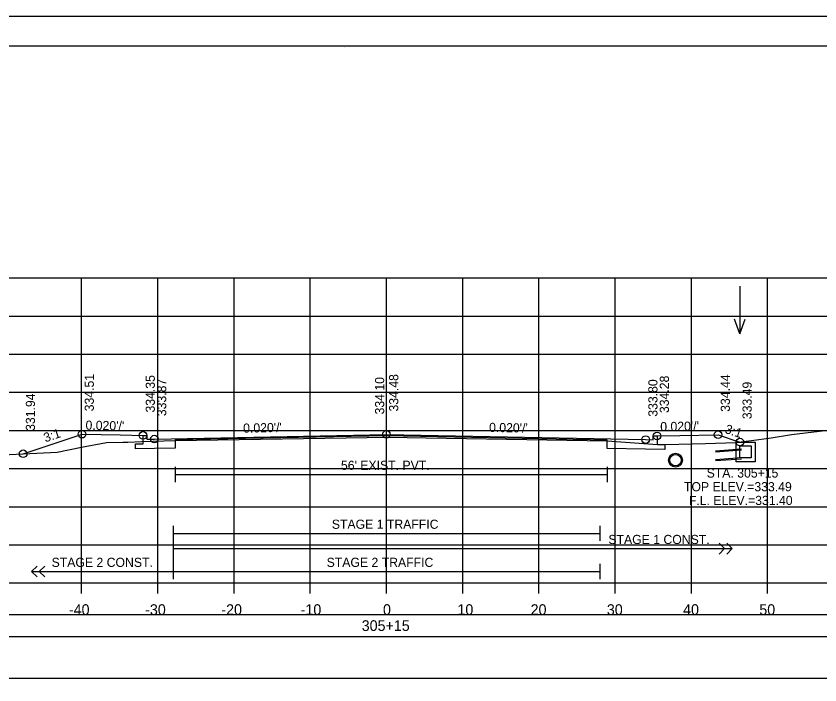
# Model space of a CAD drawing. Extents: x 1368122 to 1710785, y 373130 to 557566.
# Drawn here: x 1369307 to 1369412.4, y 373469.3 to 373557 of the extents above; entities that cross this region are included whole.
import ezdxf

# ---------------------------------------------------------------- set-up
doc = ezdxf.new("R2010")
doc.units = 0
for name, color, linetype in [('R_Alt Surface', 7, 'Continuous'), ('R_Axis', 7, 'Continuous'), ('R_Axis Annot', 7, 'Continuous'), ('R_Border', 7, 'Continuous'), ('R_Exist Surface', 7, 'Continuous'), ('R_Fin Surface', 7, 'Continuous'), ('R_Grid', 7, 'Continuous'), ('R_No Plot', 7, 'Continuous'), ('R_Striping', 7, 'Continuous'), ('R_Water', 7, 'Continuous'), ('R_Water Annot', 7, 'Continuous'), ('R_Xsect Elev', 7, 'Continuous'), ('R_Xsect Slope', 7, 'Continuous')]:
    doc.layers.add(name, color=color, linetype=linetype)

msp = doc.modelspace()

# ---------------------------------------------------------------- linework, layer by layer
for points in [[(1369206.41, 373475.64), (1369504.71, 373475.64), (1369504.71, 373478.46), (1369206.41, 373478.46)], [(1369206.41, 373470.17), (1369504.71, 373470.17), (1369504.71, 373475.58), (1369206.41, 373475.58)]]:
    msp.add_lwpolyline(points, close=True)
at = {"layer": 'R_Alt Surface'}
for points in [[(1369391.06, 373501.93), (1369391.06, 373500.84), (1369392.06, 373500.82), (1369392.06, 373500.15), (1369389.56, 373500.2), (1369384.5, 373500.3), (1369384.5, 373501.38), (1369355.56, 373501.96), (1369327.83, 373501.4), (1369327.83, 373500.32), (1369325.12, 373500.27), (1369322.62, 373500.22), (1369322.62, 373500.89), (1369323.62, 373500.91), (1369323.62, 373502)], [(1369327.83, 373497.88), (1369327.83, 373495.88)], [(1369384.5, 373497.88), (1369384.5, 373495.88)], [(1369327.83, 373496.88), (1369384.5, 373496.88)]]:
    msp.add_lwpolyline(points, dxfattribs=at)
at = {"layer": 'R_Axis'}
for p, q in [((1369205.56, 373482.65), (1369505.56, 373482.65)), ((1369315.56, 373481.25), (1369315.56, 373482.65)), ((1369325.56, 373481.25), (1369325.56, 373482.65)), ((1369335.56, 373481.25), (1369335.56, 373482.65)), ((1369345.56, 373481.25), (1369345.56, 373482.65)), ((1369355.56, 373481.25), (1369355.56, 373482.65)), ((1369365.56, 373481.25), (1369365.56, 373482.65)), ((1369375.56, 373481.25), (1369375.56, 373482.65)), ((1369385.56, 373481.25), (1369385.56, 373482.65)), ((1369395.56, 373481.25), (1369395.56, 373482.65)), ((1369405.56, 373481.25), (1369405.56, 373482.65))]:
    msp.add_line(p, q, dxfattribs=at)
at = {"layer": 'R_Border'}
for p, q in [((1369197.56, 373553.11), (1369513.74, 373553.11)), ((1369350.08, 373552.85), (1369350.08, 373552.85)), ((1369350.08, 373552.85), (1369350.08, 373552.85))]:
    msp.add_line(p, q, dxfattribs=at)
at = {"layer": 'R_Exist Surface'}
msp.add_lwpolyline([(1369301.59, 373499.29), (1369312.36, 373499.8), (1369315.54, 373500.47), (1369318.82, 373501.08), (1369320.99, 373501.12), (1369321.63, 373501.13), (1369323.42, 373501.18), (1369327.83, 373501.33), (1369350.27, 373501.66), (1369355.77, 373501.75), (1369360.75, 373501.67), (1369384.5, 373501.3), (1369391.13, 373500.82), (1369392.16, 373500.75), (1369392.17, 373500.79), (1369397.43, 373500.95), (1369401.41, 373501.06), (1369403.44, 373501.34), (1369406.04, 373501.7), (1369408.7, 373502.11), (1369423.73, 373503.92)], dxfattribs=at)
at = {"layer": 'R_Fin Surface'}
msp.add_lwpolyline([(1369307.9, 373499.59), (1369315.62, 373502.16), (1369320.62, 373502.06), (1369323.62, 373502), (1369324.12, 373502), (1369324.12, 373501.5), (1369325.12, 373501.52), (1369355.56, 373502.13), (1369389.56, 373501.45), (1369390.56, 373501.43), (1369390.56, 373501.93), (1369391.06, 373501.93), (1369394.06, 373501.99), (1369399.06, 373502.09), (1369401.92, 373501.13)], dxfattribs=at)
at = {"layer": 'R_Grid'}
for p, q in [((1369205.56, 373522.65), (1369505.56, 373522.65)), ((1369315.56, 373482.65), (1369315.56, 373522.65)), ((1369325.56, 373482.65), (1369325.56, 373522.65)), ((1369335.56, 373482.65), (1369335.56, 373522.65)), ((1369345.56, 373482.65), (1369345.56, 373522.65)), ((1369355.56, 373482.65), (1369355.56, 373522.65)), ((1369365.56, 373482.65), (1369365.56, 373522.65)), ((1369375.56, 373482.65), (1369375.56, 373522.65)), ((1369385.56, 373482.65), (1369385.56, 373522.65)), ((1369395.56, 373482.65), (1369395.56, 373522.65)), ((1369405.56, 373482.65), (1369405.56, 373522.65)), ((1369205.56, 373517.65), (1369505.56, 373517.65)), ((1369205.56, 373512.65), (1369505.56, 373512.65)), ((1369205.56, 373507.65), (1369505.56, 373507.65)), ((1369205.56, 373502.65), (1369505.56, 373502.65)), ((1369205.56, 373497.65), (1369505.56, 373497.65)), ((1369205.56, 373492.65), (1369505.56, 373492.65)), ((1369205.56, 373487.65), (1369505.56, 373487.65)), ((1369205.56, 373482.65), (1369505.56, 373482.65))]:
    msp.add_line(p, q, dxfattribs=at)
at = {"layer": 'R_No Plot'}
for p, q in [((1369185.16, 373557), (1369518.49, 373557)), ((1369402.15, 373500.19), (1369398.72, 373499.94)), ((1369402.15, 373498.9), (1369398.72, 373498.65))]:
    msp.add_line(p, q, dxfattribs=at)
for points in [[(1369185.15, 373557), (1369518.49, 373557), (1369518.49, 373343.66), (1369185.15, 373343.66)], [(1369431.48, 373553.11), (1369451.1, 373553.11), (1369451.1, 373543.23), (1369467.21, 373543.23), (1369490.41, 373543.23), (1369490.53, 373515.07), (1369513.74, 373515.07), (1369513.74, 373347.65), (1369197.56, 373347.65), (1369197.56, 373553.11)]]:
    msp.add_lwpolyline(points, close=True, dxfattribs=at)
for centre, radius in [((1369315.62, 373502.16), 0.5), ((1369323.62, 373502), 0.5), ((1369355.56, 373502.13), 0.5), ((1369391.06, 373501.93), 0.5), ((1369399.06, 373502.09), 0.5), ((1369325.12, 373501.52), 0.5), ((1369389.56, 373501.45), 0.5), ((1369401.92, 373501.13), 0.5), ((1369307.9, 373499.59), 0.5), ((1369393.48, 373498.75), 0.917)]:
    msp.add_circle(centre, radius, dxfattribs=at)
at = {"layer": 'R_Striping'}
for p, q in [((1369399.92, 373487.15), (1369399.21, 373487.85)), ((1369400.92, 373487.15), (1369400.21, 373487.85)), ((1369399.21, 373486.44), (1369399.92, 373487.15)), ((1369400.21, 373486.44), (1369400.92, 373487.15)), ((1369309.01, 373484.15), (1369309.72, 373484.85)), ((1369310.01, 373484.15), (1369310.72, 373484.85)), ((1369309.01, 373484.15), (1369327.56, 373484.15)), ((1369309.72, 373483.44), (1369309.01, 373484.15)), ((1369310.72, 373483.44), (1369310.01, 373484.15))]:
    msp.add_line(p, q, dxfattribs=at)
for points in [[(1369327.56, 373490.15), (1369327.56, 373483.15)], [(1369383.56, 373490.15), (1369383.56, 373488.15)], [(1369327.56, 373489.15), (1369383.56, 373489.15)], [(1369327.56, 373487.15), (1369400.92, 373487.15)], [(1369383.56, 373485.15), (1369383.56, 373483.15)], [(1369327.56, 373484.15), (1369383.56, 373484.15)]]:
    msp.add_lwpolyline(points, dxfattribs=at)
at = {"layer": 'R_Water'}
for p, q in [((1369402.15, 373500.05), (1369398.72, 373499.79)), ((1369402.15, 373499.05), (1369398.72, 373498.79))]:
    msp.add_line(p, q, dxfattribs=at)
for points in [[(1369402.67, 373501.13), (1369403.92, 373501.13), (1369403.92, 373498.55), (1369402.67, 373498.55), (1369401.42, 373498.55), (1369401.42, 373501.13)], [(1369402.67, 373500.63), (1369403.42, 373500.63), (1369403.42, 373499.05), (1369402.67, 373499.05), (1369401.92, 373499.05), (1369401.92, 373500.63)]]:
    msp.add_lwpolyline(points, close=True, dxfattribs=at)
msp.add_circle((1369393.48, 373498.75), 0.75, dxfattribs=at)
at = {"layer": 'R_Water Annot'}
for p, q in [((1369401.92, 373521.59), (1369401.92, 373515.31)), ((1369401.92, 373515.31), (1369401.22, 373517.23)), ((1369401.92, 373515.31), (1369402.62, 373517.23))]:
    msp.add_line(p, q, dxfattribs=at)
at = {"layer": 'R_Xsect Elev'}
msp.add_line((1369355.56, 373501.75), (1369355.56, 373511.75), dxfattribs=at)

# ---------------------------------------------------------------- texts
at = {"layer": 'R_Axis Annot'}
for s, p in [('-40', (1369313.9, 373478.45)), ('-30', (1369323.9, 373478.45)), ('-20', (1369333.9, 373478.45)), ('-10', (1369344.3, 373478.45)), ('0', (1369355.1, 373478.45)), ('10', (1369364.87, 373478.45)), ('20', (1369374.47, 373478.45)), ('30', (1369384.47, 373478.45)), ('40', (1369394.47, 373478.45)), ('50', (1369404.47, 373478.45)), ('305+15', (1369352.31, 373476.35))]:
    msp.add_text(s, height=1.4, dxfattribs=at).set_placement(p)
at = {"layer": 'R_Striping'}
for s, p in [('STAGE 1 TRAFFIC', (1369348.39, 373489.75)), ('STAGE 1 CONST.', (1369384.67, 373487.75)), ('STAGE 2 CONST.', (1369311.63, 373484.75)), ('STAGE 2 TRAFFIC', (1369347.71, 373484.75))]:
    msp.add_text(s, height=1.2, dxfattribs=at).set_placement(p)
at = {"layer": 'R_Water'}
msp.add_text("56' EXIST. PVT.", height=1.2, dxfattribs=at).set_placement((1369349.59, 373497.48))
at = {"layer": 'R_Water Annot'}
for s, p in [('STA. 305+15', (1369397.56, 373496.47)), ('TOP ELEV.=333.49', (1369394.59, 373494.67)), ('F.L. ELEV.=331.40', (1369395.23, 373492.87))]:
    msp.add_text(s, height=1.2, dxfattribs=at).set_placement(p)
at = {"layer": 'R_Xsect Elev'}
for s, p in [('334.51', (1369317.17, 373505.16)), ('334.35', (1369325.17, 373505)), ('334.10', (1369355.26, 373504.75)), ('334.48', (1369357.11, 373505.13)), ('334.28', (1369392.61, 373504.93)), ('334.44', (1369400.61, 373505.09)), ('333.87', (1369326.67, 373504.52)), ('333.80', (1369391.11, 373504.45)), ('333.49', (1369403.47, 373504.13)), ('331.94', (1369309.45, 373502.59))]:
    msp.add_text(s, height=1.2, rotation=90, dxfattribs=at).set_placement(p)
at = {"layer": 'R_Xsect Slope'}
for s, rotation, p in [("0.020'/'", 358.8542, (1369316.07, 373502.75)), ("0.020'/'", 1.1458, (1369336.77, 373502.35)), ("0.020'/'", 358.8542, (1369369.01, 373502.46)), ("0.020'/'", 1.1458, (1369391.49, 373502.54)), ('3:1', 341.5651, (1369399.86, 373502.35)), ('3:1', 18.4349, (1369310.81, 373501.08))]:
    msp.add_text(s, height=1.2, rotation=rotation, dxfattribs=at).set_placement(p)

doc.saveas('drawing.dxf')
